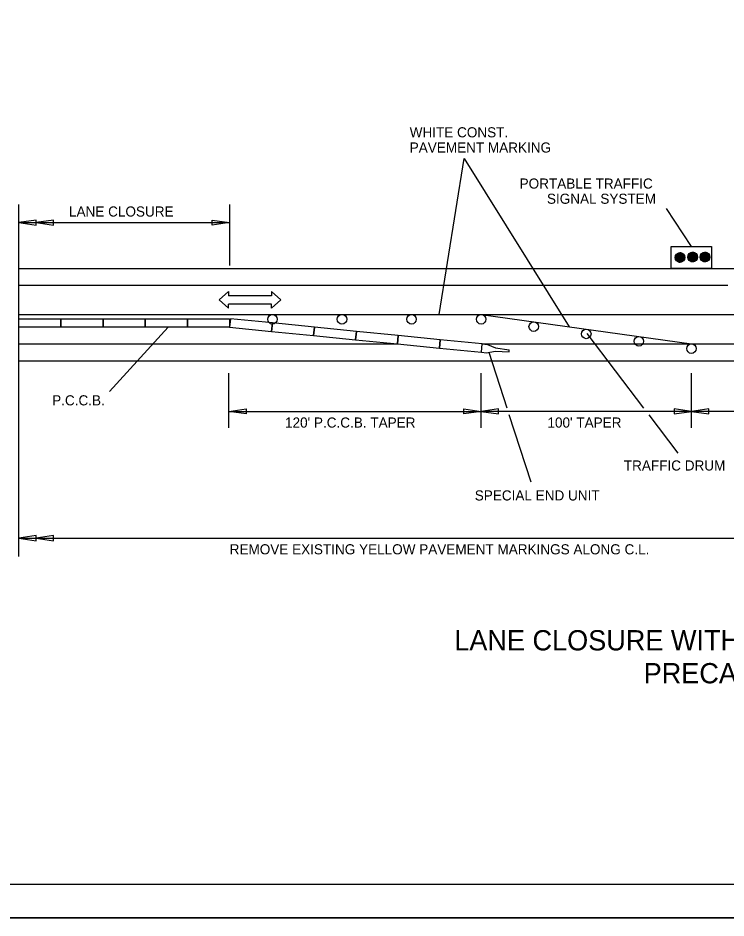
# Model space of a CAD drawing. Extents: x 1678017 to 1687792, y 404433 to 413488.
# Drawn here: x 1679931 to 1680351, y 404433 to 404967 of the extents above; entities that cross this region are included whole.
import ezdxf

# ---------------------------------------------------------------- set-up
doc = ezdxf.new("R2010")
doc.units = 0
for name, color, linetype in [('Default', 7, 'Continuous'), ('S_BUILDING', 7, 'Continuous'), ('S_GRAVEL_ROAD', 7, 'Continuous'), ('S_SHOULDER', 7, 'Continuous'), ('S_STREAM', 7, 'Continuous')]:
    doc.layers.add(name, color=color, linetype=linetype)

msp = doc.modelspace()

# ---------------------------------------------------------------- linework, layer by layer
at = {"layer": 'Default'}
for p, q in [((1679931.8, 404647.49), (1679931.8, 404856.02)), ((1680056.8, 404856.02), (1680056.8, 404819.85)), ((1680330.55, 404831.14), (1680315.71, 404853.66)), ((1679942.11, 404846.78), (1679931.8, 404845.23)), ((1679942.11, 404843.69), (1679942.11, 404846.78)), ((1679952.41, 404846.78), (1679942.11, 404845.23)), ((1679952.41, 404843.69), (1679952.41, 404846.78)), ((1680046.5, 404843.69), (1680046.5, 404846.78)), ((1680046.5, 404846.78), (1680056.8, 404845.23)), ((1679931.8, 404845.23), (1680056.8, 404845.23)), ((1679931.8, 404845.23), (1679942.11, 404843.69)), ((1679942.11, 404845.23), (1679952.41, 404843.69)), ((1680056.8, 404845.23), (1680046.5, 404843.69)), ((1680323.93, 404821.71), (1680320.92, 404824.71)), ((1680323.75, 404821.71), (1680320.92, 404824.54)), ((1680323.57, 404821.71), (1680320.93, 404824.35)), ((1680324.09, 404821.72), (1680320.94, 404824.88)), ((1680323.37, 404821.74), (1680320.95, 404824.15)), ((1680324.25, 404821.74), (1680320.96, 404825.03)), ((1680324.4, 404821.77), (1680320.98, 404825.18)), ((1680324.54, 404821.8), (1680321.02, 404825.32)), ((1680324.68, 404821.84), (1680321.06, 404825.46)), ((1680324.81, 404821.89), (1680321.1, 404825.59)), ((1680324.93, 404821.94), (1680321.15, 404825.72)), ((1680325.05, 404822), (1680321.21, 404825.84)), ((1680325.17, 404822.06), (1680321.27, 404825.96)), ((1680325.28, 404822.12), (1680321.33, 404826.07)), ((1680325.39, 404822.19), (1680321.4, 404826.18)), ((1680325.49, 404822.26), (1680321.48, 404826.28)), ((1680325.59, 404822.34), (1680321.55, 404826.38)), ((1680325.69, 404822.42), (1680321.63, 404826.48)), ((1680325.78, 404822.5), (1680321.72, 404826.57)), ((1680325.87, 404822.59), (1680321.81, 404826.66)), ((1680325.96, 404822.68), (1680321.9, 404826.74)), ((1680326.04, 404822.78), (1680322, 404826.82)), ((1680326.11, 404822.88), (1680322.1, 404826.9)), ((1680326.19, 404822.98), (1680322.2, 404826.97)), ((1680326.25, 404823.09), (1680322.31, 404827.04)), ((1680326.32, 404823.2), (1680322.42, 404827.1)), ((1680326.38, 404823.32), (1680322.54, 404827.16)), ((1680326.43, 404823.44), (1680322.66, 404827.22)), ((1680326.49, 404823.57), (1680322.78, 404827.27)), ((1680326.53, 404823.7), (1680322.91, 404827.32)), ((1680326.57, 404823.84), (1680323.05, 404827.36)), ((1680326.61, 404823.98), (1680323.19, 404827.39)), ((1680326.63, 404824.13), (1680323.34, 404827.42)), ((1680326.65, 404824.28), (1680323.5, 404827.44)), ((1680326.67, 404824.45), (1680323.66, 404827.45)), ((1680326.67, 404824.62), (1680323.84, 404827.45)), ((1680326.66, 404824.81), (1680324.02, 404827.45)), ((1680326.64, 404825.01), (1680324.22, 404827.42)), ((1680326.6, 404825.23), (1680324.44, 404827.38)), ((1680326.53, 404825.47), (1680324.69, 404827.31)), ((1680326.42, 404825.76), (1680324.97, 404827.2)), ((1680326.2, 404826.15), (1680325.36, 404826.99)), ((1680331.41, 404821.97), (1680328.41, 404824.98)), ((1680331.24, 404821.97), (1680328.41, 404824.8)), ((1680331.05, 404821.98), (1680328.41, 404824.62)), ((1680331.58, 404821.98), (1680328.42, 404825.14)), ((1680331.73, 404822), (1680328.44, 404825.3)), ((1680330.85, 404822), (1680328.44, 404824.42)), ((1680331.88, 404822.03), (1680328.47, 404825.44)), ((1680330.63, 404822.04), (1680328.48, 404824.2)), ((1680332.02, 404822.07), (1680328.5, 404825.59)), ((1680332.16, 404822.11), (1680328.54, 404825.72)), ((1680332.29, 404822.15), (1680328.59, 404825.85)), ((1680332.42, 404822.2), (1680328.64, 404825.98)), ((1680332.54, 404822.26), (1680328.7, 404826.1)), ((1680332.66, 404822.32), (1680328.76, 404826.22)), ((1680332.77, 404822.38), (1680328.82, 404826.33)), ((1680332.88, 404822.45), (1680328.89, 404826.44)), ((1680332.98, 404822.52), (1680328.96, 404826.54)), ((1680333.08, 404822.6), (1680329.04, 404826.64)), ((1680333.18, 404822.68), (1680329.12, 404826.74)), ((1680333.27, 404822.77), (1680329.2, 404826.83)), ((1680333.36, 404822.86), (1680329.29, 404826.92)), ((1680333.44, 404822.95), (1680329.38, 404827)), ((1680333.52, 404823.04), (1680329.48, 404827.08)), ((1680333.6, 404823.14), (1680329.58, 404827.16)), ((1680333.67, 404823.25), (1680329.68, 404827.23)), ((1680333.74, 404823.36), (1680329.79, 404827.3)), ((1680333.8, 404823.47), (1680329.9, 404827.37)), ((1680333.86, 404823.58), (1680330.02, 404827.43)), ((1680333.92, 404823.71), (1680330.14, 404827.48)), ((1680333.97, 404823.83), (1680330.27, 404827.53)), ((1680334.02, 404823.96), (1680330.4, 404827.58)), ((1680334.06, 404824.1), (1680330.54, 404827.62)), ((1680334.09, 404824.24), (1680330.68, 404827.65)), ((1680334.12, 404824.39), (1680330.83, 404827.68)), ((1680334.14, 404824.55), (1680330.98, 404827.7)), ((1680334.15, 404824.71), (1680331.15, 404827.71)), ((1680334.15, 404824.89), (1680331.32, 404827.72)), ((1680334.15, 404825.07), (1680331.51, 404827.71)), ((1680334.12, 404825.27), (1680331.71, 404827.69)), ((1680334.08, 404825.49), (1680331.93, 404827.64)), ((1680334.01, 404825.73), (1680332.17, 404827.58)), ((1680333.9, 404826.02), (1680332.46, 404827.46)), ((1680333.69, 404826.41), (1680332.85, 404827.25)), ((1680338.59, 404821.97), (1680335.67, 404824.88)), ((1680338.76, 404821.98), (1680335.68, 404825.05)), ((1680338.41, 404821.97), (1680335.68, 404824.7)), ((1680338.21, 404821.99), (1680335.69, 404824.51)), ((1680338.92, 404821.99), (1680335.7, 404825.21)), ((1680339.07, 404822.02), (1680335.72, 404825.36)), ((1680338, 404822.02), (1680335.73, 404824.3)), ((1680339.22, 404822.05), (1680335.75, 404825.51)), ((1680339.36, 404822.08), (1680335.79, 404825.65)), ((1680339.49, 404822.13), (1680335.83, 404825.78)), ((1680339.62, 404822.17), (1680335.88, 404825.91)), ((1680339.74, 404822.23), (1680335.93, 404826.04)), ((1680339.86, 404822.28), (1680335.99, 404826.15)), ((1680339.98, 404822.35), (1680336.05, 404826.27)), ((1680340.09, 404822.41), (1680336.12, 404826.38)), ((1680340.19, 404822.48), (1680336.19, 404826.49)), ((1680340.29, 404822.56), (1680336.26, 404826.59)), ((1680340.39, 404822.64), (1680336.34, 404826.69)), ((1680340.49, 404822.72), (1680336.43, 404826.78)), ((1680340.58, 404822.81), (1680336.51, 404826.87)), ((1680340.66, 404822.9), (1680336.6, 404826.96)), ((1680340.75, 404822.99), (1680336.7, 404827.04)), ((1680340.83, 404823.09), (1680336.79, 404827.12)), ((1680340.9, 404823.19), (1680336.9, 404827.19)), ((1680340.97, 404823.29), (1680337, 404827.27)), ((1680341.04, 404823.4), (1680337.11, 404827.33)), ((1680341.1, 404823.52), (1680337.23, 404827.39)), ((1680341.16, 404823.64), (1680337.34, 404827.45)), ((1680341.26, 404823.89), (1680337.6, 404827.55)), ((1680341.3, 404824.02), (1680337.73, 404827.6)), ((1680341.34, 404824.16), (1680337.87, 404827.64)), ((1680341.37, 404824.31), (1680338.01, 404827.67)), ((1680341.4, 404824.46), (1680338.17, 404827.69)), ((1680341.42, 404824.62), (1680338.33, 404827.71)), ((1680341.42, 404824.79), (1680338.49, 404827.72)), ((1680341.42, 404824.97), (1680338.67, 404827.71)), ((1680341.41, 404825.16), (1680338.86, 404827.7)), ((1680341.38, 404825.37), (1680339.07, 404827.67)), ((1680341.32, 404825.59), (1680339.3, 404827.62)), ((1680341.24, 404825.85), (1680339.56, 404827.53)), ((1680341.1, 404826.18), (1680339.88, 404827.39)), ((1680340.71, 404826.74), (1680340.44, 404827.01)), ((1680323.15, 404821.78), (1680320.99, 404823.93)), ((1680322.91, 404821.85), (1680321.06, 404823.69)), ((1680322.62, 404821.96), (1680321.17, 404823.4)), ((1680322.23, 404822.17), (1680321.38, 404823.01)), ((1680330.39, 404822.11), (1680328.55, 404823.95)), ((1680330.1, 404822.22), (1680328.66, 404823.67)), ((1680329.71, 404822.43), (1680328.87, 404823.28)), ((1680337.77, 404822.07), (1680335.78, 404824.07)), ((1680337.51, 404822.16), (1680335.87, 404823.8)), ((1680337.18, 404822.32), (1680336.02, 404823.47)), ((1679931.8, 404818.16), (1680081.8, 404818.16)), ((1680081.8, 404818.15), (1680990.32, 404818.15)), ((1679931.8, 404808.16), (1680081.8, 404808.16)), ((1680081.8, 404808.15), (1680352.09, 404808.15)), ((1679931.8, 404790.77), (1680453.01, 404790.77)), ((1680205.92, 404790.77), (1680330.55, 404773.39)), ((1679985.52, 404745.16), (1680020.35, 404783.27)), ((1680268.55, 404779.45), (1680302.16, 404735.39)), ((1679931.8, 404773.39), (1680081.8, 404773.39)), ((1680081.8, 404773.39), (1680156.05, 404773.39)), ((1680206.5, 404773.39), (1680452.34, 404773.39)), ((1680221.25, 404735.39), (1680210.59, 404768.36)), ((1679931.8, 404763.39), (1680081.8, 404763.39)), ((1680081.8, 404763.39), (1680990.32, 404763.39)), ((1680056.3, 404723.6), (1680056.3, 404755.94)), ((1680205.92, 404723.6), (1680205.92, 404755.94)), ((1680330.55, 404723.6), (1680330.55, 404755.94)), ((1680056.3, 404733.39), (1680066.61, 404734.93)), ((1680066.61, 404734.93), (1680066.61, 404731.84)), ((1680195.61, 404731.84), (1680195.61, 404734.93)), ((1680195.61, 404734.93), (1680205.92, 404733.39)), ((1680216.22, 404734.93), (1680205.92, 404733.39)), ((1680216.22, 404731.84), (1680216.22, 404734.93)), ((1680330.55, 404733.39), (1680320.25, 404734.93)), ((1680320.25, 404734.93), (1680320.25, 404731.84)), ((1680340.86, 404734.93), (1680330.55, 404733.39)), ((1680340.86, 404731.84), (1680340.86, 404734.93)), ((1680056.3, 404733.39), (1680205.92, 404733.39)), ((1680066.61, 404731.84), (1680056.3, 404733.39)), ((1680205.92, 404733.39), (1680195.61, 404731.84)), ((1680205.92, 404733.39), (1680216.22, 404731.84)), ((1680330.55, 404733.39), (1680205.92, 404733.39)), ((1680235.49, 404691.36), (1680222.54, 404731.39)), ((1680305.21, 404731.39), (1680322.5, 404708.72)), ((1680320.25, 404731.84), (1680330.55, 404733.39)), ((1680330.55, 404733.39), (1680340.86, 404731.84)), ((1680455.16, 404733.39), (1680330.55, 404733.39)), ((1679942.11, 404659.82), (1679931.8, 404658.28)), ((1679942.11, 404656.73), (1679942.11, 404659.82)), ((1679952.41, 404659.82), (1679942.11, 404658.28)), ((1679952.41, 404656.73), (1679952.41, 404659.82)), ((1679931.8, 404658.28), (1680455.16, 404658.28)), ((1679931.8, 404658.28), (1679942.11, 404656.73)), ((1679942.11, 404658.28), (1679952.41, 404656.73))]:
    msp.add_line(p, q, dxfattribs=at)
for points in [[(1680180.99, 404790.77), (1680195.9, 404883.22), (1680258.14, 404783.49)], [(1679931.8, 404790.77), (1680205.92, 404790.77)]]:
    msp.add_lwpolyline(points, dxfattribs=at)
msp.add_lwpolyline([(1680318.56, 404818.15), (1680318.56, 404831.14), (1680342.54, 404831.14), (1680342.54, 404818.15)], close=True, dxfattribs=at)
for centre, radius in [((1680323.79, 404824.58), 2.87), ((1680331.28, 404824.84), 2.87), ((1680338.55, 404824.84), 2.87), ((1680082.18, 404787.96), 2.81), ((1680123.42, 404787.96), 2.81), ((1680164.67, 404787.96), 2.81), ((1680205.92, 404787.96), 2.81), ((1680237.07, 404783.61), 2.81), ((1680268.23, 404779.27), 2.81), ((1680299.39, 404774.92), 2.81), ((1680330.55, 404770.57), 2.81)]:
    msp.add_circle(centre, radius, dxfattribs=at)
at = {"layer": 'S_BUILDING'}
msp.add_line((1681251.51, 404453.08), (1679670.61, 404453.08), dxfattribs=at)
at = {"layer": 'S_GRAVEL_ROAD'}
for p, q in [((1680050.64, 404799.46), (1680056.12, 404804.46)), ((1680056.12, 404804.46), (1680056.12, 404801.96)), ((1680081.6, 404804.46), (1680087.08, 404799.46)), ((1680081.6, 404804.46), (1680081.6, 404801.96)), ((1680056.12, 404794.46), (1680050.64, 404799.46)), ((1680081.6, 404801.96), (1680056.12, 404801.96)), ((1680087.08, 404799.46), (1680081.6, 404794.46)), ((1680081.6, 404796.96), (1680056.12, 404796.96)), ((1680056.12, 404794.46), (1680056.12, 404796.96)), ((1680081.6, 404794.46), (1680081.6, 404796.96))]:
    msp.add_line(p, q, dxfattribs=at)
at = {"layer": 'S_SHOULDER'}
for p, q in [((1680206.06, 404768.4), (1680206.56, 404773.38)), ((1680206.56, 404773.38), (1680209.67, 404773.07)), ((1680209.67, 404773.07), (1680214.5, 404771.11)), ((1680214.5, 404771.11), (1680222.54, 404769.9)), ((1680206.06, 404768.4), (1680209.17, 404768.09)), ((1680209.17, 404768.09), (1680214.3, 404769.07)), ((1680214.3, 404769.07), (1680222.42, 404768.66)), ((1680222.42, 404768.66), (1680222.54, 404769.9))]:
    msp.add_line(p, q, dxfattribs=at)
for points in [[(1679931.8, 404788.27), (1679956.8, 404788.27), (1679956.8, 404783.27), (1679931.8, 404783.27)], [(1679956.8, 404788.27), (1679981.8, 404788.27), (1679981.8, 404783.27), (1679956.8, 404783.27)], [(1679981.8, 404788.27), (1680006.8, 404788.27), (1680006.8, 404783.27), (1679981.8, 404783.27)], [(1680006.8, 404788.27), (1680031.8, 404788.27), (1680031.8, 404783.27), (1680006.8, 404783.27)], [(1680031.8, 404788.27), (1680056.8, 404788.27), (1680056.8, 404783.27), (1680031.8, 404783.27)], [(1680082.18, 404785.77), (1680057.3, 404788.25), (1680056.8, 404783.27), (1680081.68, 404780.79)], [(1680107.05, 404783.29), (1680082.18, 404785.77), (1680081.68, 404780.79), (1680106.56, 404778.31)], [(1680131.93, 404780.81), (1680107.05, 404783.29), (1680106.56, 404778.31), (1680131.43, 404775.84)], [(1680156.81, 404778.33), (1680131.93, 404780.81), (1680131.43, 404775.84), (1680156.31, 404773.36)], [(1680181.68, 404775.86), (1680156.81, 404778.33), (1680156.31, 404773.36), (1680181.19, 404770.88)], [(1680206.56, 404773.38), (1680181.68, 404775.86), (1680181.19, 404770.88), (1680206.06, 404768.4)]]:
    msp.add_lwpolyline(points, close=True, dxfattribs=at)
at = {"layer": 'S_STREAM'}
msp.add_line((1679608.61, 404433.19), (1681275.28, 404433.19), dxfattribs=at)
for points in [[(1679608.58, 405499.86), (1681275.28, 405499.86), (1681275.28, 404433.17), (1679608.58, 404433.17)], [(1680840.21, 405480.38), (1680938.31, 405480.38), (1680938.31, 405430.98), (1681018.87, 405430.98), (1681134.87, 405430.98), (1681134.87, 405309.32), (1681251.51, 405309.32), (1681251.51, 404453.08), (1679670.61, 404453.08), (1679670.61, 405480.38)]]:
    msp.add_lwpolyline(points, close=True, dxfattribs=at)

# ---------------------------------------------------------------- texts
at = {"layer": 'Default'}
for s, height, p in [('WHITE CONST.', 6, (1680163.55, 404895.77)), ('PAVEMENT MARKING', 6, (1680163.55, 404886.77)), ('PORTABLE TRAFFIC', 6, (1680228.71, 404865.41)), ('SIGNAL SYSTEM', 6, (1680244.91, 404856.41)), ('LANE CLOSURE', 6, (1679961.61, 404848.84)), ('P.C.C.B.', 6, (1679951.62, 404736.94)), ("120' P.C.C.B. TAPER", 6, (1680089.65, 404723.78)), ("100' TAPER", 6, (1680245.2, 404723.78)), ('TRAFFIC DRUM', 6, (1680290.49, 404698.33)), ('SPECIAL END UNIT', 6, (1680202.12, 404680.59)), ('REMOVE EXISTING YELLOW PAVEMENT MARKINGS ALONG C.L.', 6, (1680056.85, 404648.66)), ('LANE CLOSURE WITH PORTABLE TRAFFIC SIGNAL SYSTEM &', 12, (1680189.98, 404591.74)), ('PRECAST CONCRETE BARRIER WALL', 12, (1680302.23, 404572.24))]:
    msp.add_text(s, height=height, dxfattribs=at).set_placement(p)

doc.saveas('drawing.dxf')
